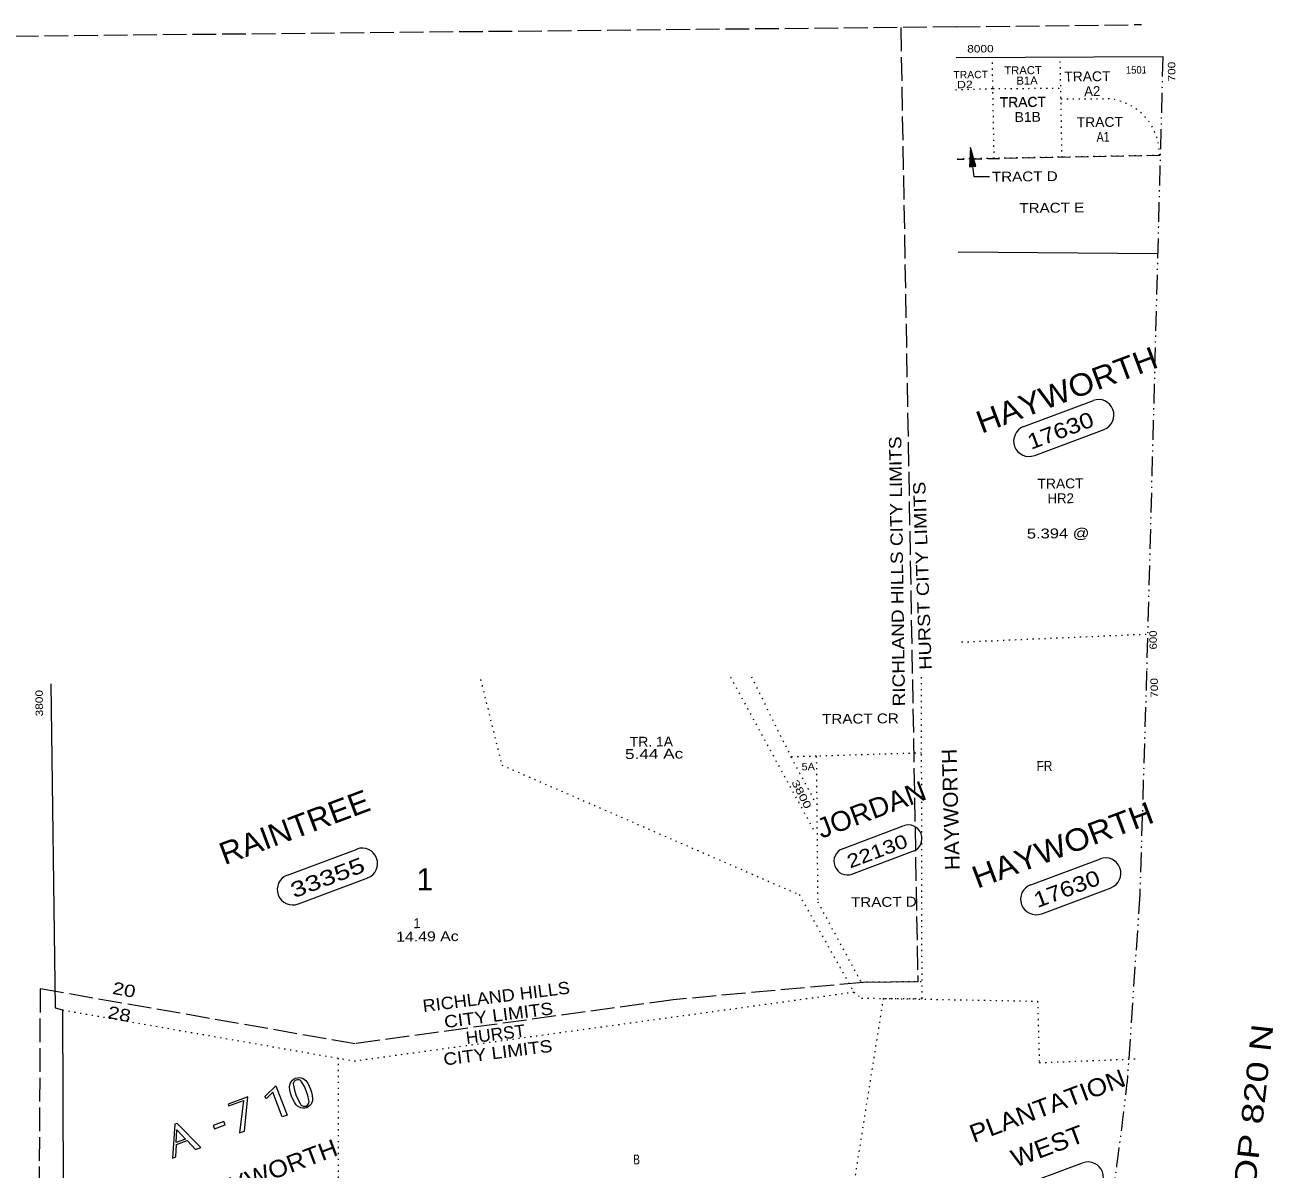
# Model space of a CAD drawing. Extents: x 2356373 to 2371954, y 6966197 to 6989612.
# Drawn here: x 2364359 to 2366382, y 6984068 to 6985921 of the extents above; entities that cross this region are included whole.
import ezdxf
from ezdxf.enums import TextEntityAlignment as Align

# ---------------------------------------------------------------- set-up
doc = ezdxf.new("R2010")
doc.units = 0
doc.header["$LTSCALE"] = 6.4
for name, pattern in [('DASH_DOUBLE_DOT', [9.2, 5, -1.2, 0.3, -1.2, 0.3, -1.2]), ('DOTTED', [1.5, 0.3, -1.2]), ('LONG_DASHED', [7.5, 6, -1.5]), ('MEDIUM_DASHED', [4.5, 3, -1.5])]:
    doc.linetypes.add(name, pattern=pattern)
for name, color, linetype in [('10', 7, 'Continuous'), ('11', 7, 'Continuous'), ('18', 7, 'Continuous'), ('20', 7, 'Continuous'), ('22', 7, 'Continuous'), ('24', 7, 'Continuous'), ('26', 7, 'Continuous'), ('31', 7, 'Continuous')]:
    doc.layers.add(name, color=color, linetype=linetype)
for name, color, linetype, lineweight in [('12', 7, 'Continuous', 13), ('15', 7, 'Continuous', 13), ('16', 7, 'DOTTED', 13), ('17', 7, 'Continuous', 13), ('19', 7, 'Continuous', 13), ('27', 7, 'LONG_DASHED', 13), ('35', 7, 'DOTTED', 13), ('37', 7, 'DOTTED', 13), ('6', 7, 'DOTTED', 13)]:
    doc.layers.add(name, color=color, linetype=linetype, lineweight=lineweight)

msp = doc.modelspace()

# ---------------------------------------------------------------- linework, layer by layer
at = {"layer": '12'}
msp.add_lwpolyline([(2365922.639, 6985674.758), (2365897.649, 6985674.512), (2365892.182, 6985722.246), (2365890.492, 6985690.638), (2365900.478, 6985691.836), (2365892.182, 6985722.246)], dxfattribs=at)
for points in [[(2365893.266, 6985713.559), (2365892.475, 6985692.357), (2365899.465, 6985693.125)], [(2365894.349, 6985705.171), (2365893.459, 6985694.065), (2365897.453, 6985694.505)]]:
    msp.add_lwpolyline(points, close=True, dxfattribs=at)
at = {"layer": '15'}
msp.add_line((2365868.755, 6985868.077), (2366203.652, 6985869.367), dxfattribs=at)
at = {"layer": '15', "linetype": 'DASH_DOUBLE_DOT'}
msp.add_line((2366203.652, 6985869.367), (2366177.435, 6984874.375), dxfattribs=at)
at = {"layer": '15', "linetype": 'DOTTED'}
for p, q in [((2365502.714, 6984864.349), (2365640.154, 6984612.265)), ((2365536.702, 6984864.682), (2365600.959, 6984735.048)), ((2365600.959, 6984735.048), (2365641.7, 6984658.47))]:
    msp.add_line(p, q, dxfattribs=at)
at = {"layer": '15', "linetype": 'DASH_DOUBLE_DOT'}
msp.add_lwpolyline([(2366177.435, 6984874.375), (2366166.372, 6984512.763), (2366145.785, 6984207.521)], dxfattribs=at)
at = {"layer": '15'}
msp.add_lwpolyline([(2364401.114, 6984853.528), (2364408.272, 6984328.439), (2364420.301, 6984325.157), (2364423.673, 6983472.918), (2364412.679, 6983472.611), (2364418.726, 6982146.493)], dxfattribs=at)
at = {"layer": '15', "linetype": 'DASH_DOUBLE_DOT'}
msp.add_arc((2361330.102, 6984734.687), 4844.449, 342.37406, 353.75276, dxfattribs=at)
at = {"layer": '16'}
for p, q in [((2365813.436, 6984343.84), (2365812.481, 6984867.451)), ((2365641.936, 6984736.25), (2365600.959, 6984735.048)), ((2364892.986, 6984242.624), (2365702.673, 6984354.15))]:
    msp.add_line(p, q, dxfattribs=at)
for points in [[(2365097.862, 6984860.372), (2365132.213, 6984721.846), (2365614.146, 6984512.037), (2365702.673, 6984354.15)], [(2365641.936, 6984736.25), (2365644.255, 6984500.136), (2365714.171, 6984370.409), (2365813.385, 6984371.382)], [(2365702.673, 6984354.15), (2365715.459, 6984344.077), (2365813.436, 6984343.84)]]:
    msp.add_lwpolyline(points, dxfattribs=at)
at = {"layer": '17'}
for p, q in [((2365978.6, 6985270.114), (2366091.157, 6985312.31)), ((2365996.055, 6985223.299), (2366108.611, 6985265.494)), ((2365684.396, 6984586.408), (2365783.006, 6984623.467)), ((2364785.055, 6984543.683), (2364897.612, 6984585.877)), ((2365699.798, 6984545.17), (2365798.407, 6984582.329)), ((2365989.89, 6984527.924), (2366102.447, 6984570.019)), ((2364802.511, 6984496.867), (2364915.067, 6984539.061)), ((2366007.344, 6984481.108), (2366119.901, 6984523.203)), ((2365960.738, 6984035.171), (2366073.293, 6984077.365))]:
    msp.add_line(p, q, dxfattribs=at)
for points in [[(2364824.884, 6984186.569), (2364825.436, 6984181.277), (2364825.466, 6984178.226), (2364824.495, 6984175.269), (2364823.022, 6984172.555), (2364821.046, 6984170.186), (2364818.566, 6984168.262), (2364816.08, 6984166.889), (2364813.087, 6984166.108), (2364809.59, 6984165.925), (2364806.587, 6984166.445), (2364804.077, 6984167.521), (2364801.062, 6984169.14), (2364799.041, 6984171.32), (2364795.998, 6984175.738), (2364793.453, 6984180.412), (2364791.407, 6984185.291), (2364789.857, 6984190.324), (2364788.806, 6984195.511), (2364788.255, 6984200.807), (2364788.724, 6984203.811), (2364789.696, 6984206.668), (2364791.172, 6984209.232), (2364793.147, 6984211.551), (2364795.629, 6984213.375), (2364798.115, 6984214.699), (2364801.107, 6984215.477), (2364804.104, 6984215.658), (2364807.107, 6984215.237), (2364810.115, 6984214.318), (2364812.63, 6984212.792), (2364814.648, 6984210.813), (2364817.692, 6984206.394), (2364820.236, 6984201.719), (2364822.285, 6984196.792), (2364823.833, 6984191.757), (2364824.884, 6984186.569)], [(2364801.449, 6984180.641), (2364805.516, 6984173.683), (2364806.535, 6984171.692), (2364808.049, 6984170.208), (2364810.558, 6984169.334), (2364812.559, 6984169.104), (2364815.053, 6984169.577), (2364817.043, 6984170.697), (2364818.525, 6984172.36), (2364819.506, 6984174.42), (2364819.983, 6984176.674), (2364819.461, 6984178.919), (2364817.886, 6984186.651), (2364815.313, 6984194.173), (2364812.241, 6984201.442), (2364808.175, 6984208.399), (2364807.159, 6984210.038), (2364805.646, 6984211.324), (2364803.638, 6984212.055), (2364801.139, 6984212.18), (2364799.144, 6984211.711), (2364797.154, 6984210.69), (2364795.669, 6984209.176), (2364794.688, 6984207.367), (2364794.208, 6984205.263), (2364794.73, 6984203.169), (2364796.305, 6984195.437), (2364798.379, 6984187.908), (2364801.449, 6984180.641)], [(2364714.979, 6984128.905), (2364720.435, 6984184.244), (2364688.559, 6984172.384), (2364689.586, 6984169.745), (2364713.491, 6984178.726), (2364707.012, 6984125.877), (2364714.979, 6984128.905)], [(2364766.245, 6984202.29), (2364784.207, 6984154.879), (2364776.238, 6984151.8), (2364760.85, 6984191.839), (2364750.95, 6984181.895), (2364747.918, 6984185.264), (2364766.245, 6984202.29)], [(2364681.835, 6984144.574), (2364664.403, 6984138.105), (2364666.454, 6984132.777), (2364683.887, 6984139.247), (2364681.835, 6984144.574)], [(2364644.259, 6984102.468), (2364605.888, 6984141.33), (2364602.401, 6984140.045), (2364598.44, 6984085.272), (2364603.918, 6984087.376), (2364604.72, 6984107.477), (2364622.152, 6984113.897), (2364635.793, 6984099.236), (2364644.259, 6984102.468)], [(2364605.487, 6984131.129), (2364619.63, 6984116.121), (2364604.689, 6984110.577), (2364605.487, 6984131.129)]]:
    msp.add_lwpolyline(points, close=True, dxfattribs=at)
for centre, radius, start, end in [((2366099.384, 6985288.897), 24.992, 290.56276, 110.56276), ((2365986.828, 6985246.703), 24.992, 110.56276, 290.56276), ((2365791.206, 6984602.853), 21.993, 290.56276, 110.56276), ((2364905.839, 6984562.465), 24.992, 290.56276, 110.56276), ((2365692.597, 6984565.794), 21.993, 110.56276, 290.56276), ((2366110.674, 6984546.606), 24.992, 290.56276, 110.56276), ((2364793.284, 6984520.27), 24.992, 110.56276, 290.56276), ((2365998.117, 6984504.512), 24.992, 110.56276, 290.56276), ((2366082.521, 6984053.961), 24.992, 290.56276, 110.56276)]:
    msp.add_arc(centre, radius, start, end, dxfattribs=at)
at = {"layer": '27'}
for p, q in [((2365869.27, 6985917.468), (2363239.686, 6985891.187)), ((2365778.85, 6985916.564), (2365806.482, 6984370.764)), ((2365869.27, 6985917.468), (2366169.15, 6985921.414)), ((2365718.515, 6984369.9), (2365409.875, 6984341.676)), ((2364383.975, 6984359.392), (2364379.384, 6983503.475)), ((2364894.714, 6984270.234), (2364383.975, 6984359.392)), ((2365409.875, 6984341.676), (2364891.714, 6984270.203))]:
    msp.add_line(p, q, dxfattribs=at)
at = {"layer": '27', "linetype": 'Continuous'}
msp.add_line((2365806.482, 6984370.764), (2365718.515, 6984369.9), dxfattribs=at)
at = {"layer": '35'}
for p, q in [((2365930.308, 6985704.184), (2365927.338, 6985864.544)), ((2366040.268, 6985706.214), (2366037.308, 6985866.694))]:
    msp.add_line(p, q, dxfattribs=at)
at = {"layer": '35', "linetype": 'MEDIUM_DASHED'}
msp.add_line((2366198.228, 6985709.354), (2365870.318, 6985702.724), dxfattribs=at)
at = {"layer": '37'}
for p, q in [((2365867.928, 6985815.864), (2365928.208, 6985817.674)), ((2365928.208, 6985817.674), (2366038.198, 6985818.374)), ((2366038.518, 6985801.154), (2366107.088, 6985801.284))]:
    msp.add_line(p, q, dxfattribs=at)
msp.add_arc((2366108.258, 6985711.305), 89.989, 358.75904, 90.7433, dxfattribs=at)
at = {"layer": '6'}
for p, q in [((2366198.226, 6985709.356), (2365870.371, 6985703.536)), ((2365877.506, 6984921.226), (2366176.95, 6984934.043)), ((2365812.711, 6984741.307), (2365641.936, 6984736.25)), ((2364420.301, 6984325.157), (2364892.986, 6984242.624)), ((2364866.946, 6984247.267), (2364867.551, 6983473.28)), ((2366158.82, 6984245.32), (2366003.492, 6984239.284))]:
    msp.add_line(p, q, dxfattribs=at)
at = {"layer": '6', "linetype": 'Continuous'}
msp.add_line((2365871.845, 6985553.39), (2366195.256, 6985550.589), dxfattribs=at)
at = {"layer": '6'}
for points in [[(2365750.492, 6984343.991), (2365699.836, 6984025.199), (2365737.395, 6983700.615), (2366062.382, 6983698.258)], [(2365750.492, 6984343.991), (2366000.52, 6984339.348), (2366003.492, 6984239.284)]]:
    msp.add_lwpolyline(points, dxfattribs=at)

# ---------------------------------------------------------------- texts
at = {"layer": '10', "width": 1.05}
msp.add_text('TR. 1A', height=15.99, rotation=0.563, dxfattribs=at).set_placement((2365339.866, 6984751.478))
at = {"layer": '11'}
for s, width, p in [('5.394 @', 1.25, (2365983.381, 6985088.712)), ('5.44 Ac', 1.3, (2365332.064, 6984731.607)), ('14.49 Ac', 1.2, (2364961.068, 6984435.84))]:
    msp.add_text(s, height=15.99, rotation=0.563, dxfattribs=dict(at, width=width)).set_placement(p)
at = {"layer": '12'}
for s, height, width, p in [('TRACT', 15.99, 1.05, (2365939.525, 6985787.793)), ('TRACT D', 15.99, 1.15, (2365926.717, 6985666.801)), ('TRACT E', 15.99, 1.15, (2365971.204, 6985616.051)), ('TRACT', 15.99, 1.05, (2366000.582, 6985169.559)), ('TRACT CR', 15.99, 1.15, (2365651.42, 6984788.43)), ('5A', 12, 1.1, (2365618.166, 6984713.323)), ('FR', 15.99, 0.9, (2365999.077, 6984712.264)), ('TRACT D', 15.99, 1.15, (2365698.322, 6984491.669)), ('B', 15.99, 0.75, (2365345.512, 6984074.913))]:
    msp.add_text(s, height=height, rotation=0.563, dxfattribs=dict(at, width=width)).set_placement(p)
for s, p in [('HR2', (2366016.813, 6985145.725)), ('1', (2364988.847, 6984457.609))]:
    msp.add_text(s, height=15.99, rotation=0.563, dxfattribs=at).set_placement(p)
at = {"layer": '17'}
for s, height, width, p in [('17630', 24.99, 1.2, (2365989.967, 6985232.437)), ('22130', 21.99, 1.25, (2365696.71, 6984554.137)), ('33355', 24.99, 1.35, (2364795.423, 6984505.894)), ('17630', 24.99, 1.2, (2366000.258, 6984490.137))]:
    msp.add_text(s, height=height, rotation=20.563, dxfattribs=dict(at, width=width)).set_placement(p)
at = {"layer": '18'}
for s, height, rotation, width, p in [('HAYWORTH', 35.99, 20.563, 1.1, (2365909.734, 6985258.442)), ('HAYWORTH', 23.99, 91.593, 1.05, (2365874.683, 6984552.086)), ('JORDAN', 31.99, 20.563, 1.05, (2365650.249, 6984602.368)), ('RAINTREE', 35.99, 20.563, 1.05, (2364682.927, 6984559.575)), ('HAYWORTH', 35.99, 20.563, 1.1, (2365902.977, 6984521.373)), ('PLANTATION', 28.79, 20.563, 1.1, (2365897.023, 6984109.723)), ('WEST', 28.79, 20.563, 1.1, (2365964.399, 6984069.597))]:
    msp.add_text(s, height=height, rotation=rotation, dxfattribs=dict(at, width=width)).set_placement(p)
at = {"layer": '19', "width": 1.3}
msp.add_text('E LOOP 820 N', height=34.98, rotation=83.652, dxfattribs=at).set_placement((2366337.995, 6983897.014))
at = {"layer": '20', "width": 1.1}
msp.add_text('S.HAYWORTH', height=27.99, rotation=20.563, dxfattribs=at).set_placement((2364607.518, 6983992.585))
at = {"layer": '22'}
msp.add_text('1', height=35.99, rotation=0.563, dxfattribs=at).set_placement((2364994.247, 6984518.645))
at = {"layer": '24'}
for s, rotation, width, p in [('8000', 0.563, 1.2, (2365886.674, 6985875.95)), ('1501', 0.563, 0.95, (2366143.94, 6985841.788)), ('700', 90.563, 1.2, (2366224.043, 6985829.078)), ('600', 90.563, 1.15, (2366194.09, 6984909.129)), ('700', 90.563, 1.2, (2366195.859, 6984830.768)), ('3800', 90.563, 1.2, (2364388.636, 6984800.72)), ('3800', 296.973, 1.4, (2365601.359, 6984694.263))]:
    msp.add_text(s, height=12, rotation=rotation, dxfattribs=dict(at, width=width)).set_placement(p)
at = {"layer": '26'}
for s, rotation, width, p in [('RICHLAND HILLS CITY LIMITS', 90.82, 1.15, (2365785.942, 6984817.019)), ('HURST CITY LIMITS', 91.993, 1.2, (2365829.151, 6984876.551)), ('20', 349.253, 1.25, (2364500.02, 6984351.533)), ('28', 349.253, 1.25, (2364492.408, 6984312.27))]:
    msp.add_text(s, height=19.99, rotation=rotation, dxfattribs=dict(at, width=width)).set_placement(p)
for s, width, p in [('RICHLAND HILLS', 1.1, (2365124.449, 6984336.746)), ('CITY LIMITS', 1.15, (2365128.231, 6984306.991)), ('HURST', 1.05, (2365123.231, 6984276.075)), ('CITY LIMITS', 1.15, (2365127.013, 6984246.32))]:
    msp.add_text(s, height=19.99, rotation=7.245, dxfattribs=dict(at, width=width)).set_placement(p, align=Align.CENTER)
at = {"layer": '31'}
for s, height, width, p in [('TRACT', 11.99, 1.05, (2365864.248, 6985833.924)), ('TRACT', 12.99, 1.05, (2365946.748, 6985840.494)), ('TRACT', 15.99, 1.05, (2366044.008, 6985828.934)), (' D2', 11.99, 1.25, (2365864.438, 6985818.064)), ('B1A', 12.99, 1.05, (2365966.438, 6985823.954)), ('TRACT', 15.99, 1.05, (2365939.278, 6985787.164)), ('B1B', 15.99, 1.05, (2365963.568, 6985763.464)), ('TRACT', 15.99, 1.05, (2366064.208, 6985754.974)), ('A1', 15.99, 0.8, (2366096.488, 6985731.374))]:
    msp.add_text(s, height=height, rotation=0.705, dxfattribs=dict(at, width=width)).set_placement(p)
msp.add_text('A2', height=15.99, rotation=0.705, dxfattribs=at).set_placement((2366076.288, 6985805.334))

doc.saveas('drawing.dxf')
